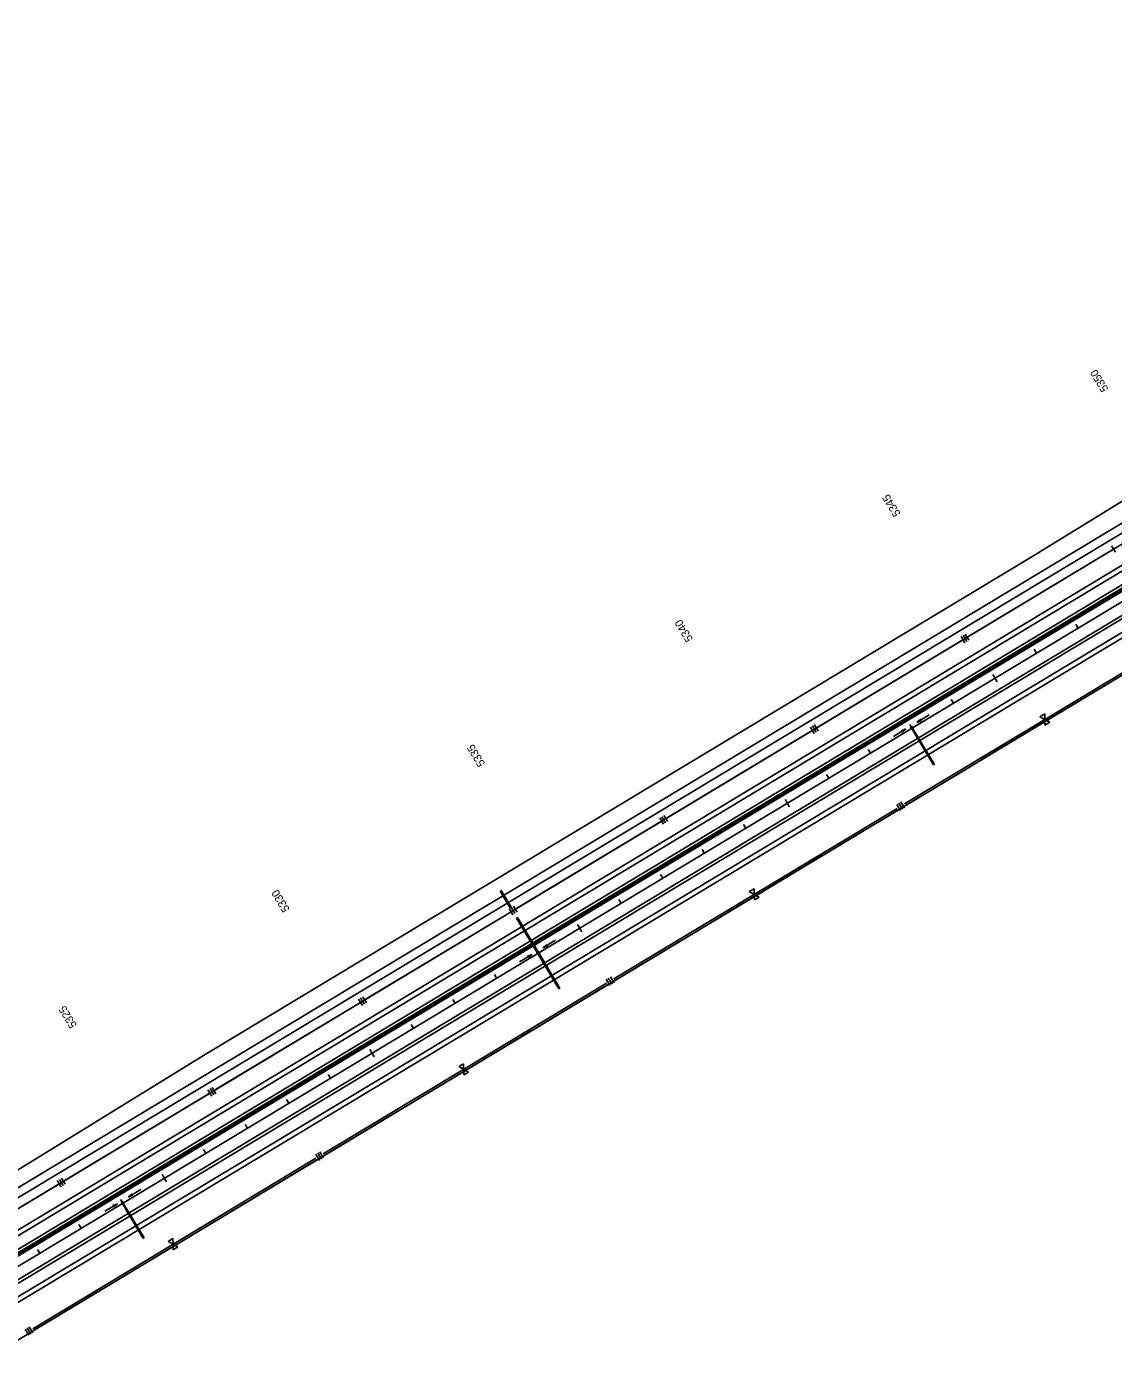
# Model space of a CAD drawing. Extents: x 192699 to 285914, y 194342 to 233219.
# Drawn here: x 275961 to 278202, y 228812 to 231567 of the extents above; entities that cross this region are included whole.
import ezdxf

# ---------------------------------------------------------------- set-up
doc = ezdxf.new("R2010")
doc.units = 0
for name, color, linetype in [('CENT LINE', 7, 'Continuous'), ('CONCRETE', 7, 'Continuous'), ('DRAINAGE', 7, 'Continuous'), ('DRAINAGE ARROWS', 7, 'Continuous'), ('R-W - CofA', 7, 'Continuous'), ('R_Water Annot', 7, 'Continuous'), ('ROAD', 7, 'Continuous'), ('SHOULDER', 7, 'Continuous'), ('STATIONING1', 7, 'Continuous'), ('WRSF', 7, 'Continuous')]:
    doc.layers.add(name, color=color, linetype=linetype)

msp = doc.modelspace()

# ---------------------------------------------------------------- linework, layer by layer
at = {"layer": 'CENT LINE'}
msp.add_line((271911, 226585.9), (279924.8, 231407.4), dxfattribs=at)
at = {"layer": 'CONCRETE'}
for p, q in [((271899.7, 226604.7), (279913.5, 231426.2)), ((271901.8, 226601.3), (279915.5, 231422.8))]:
    msp.add_line(p, q, dxfattribs=at)
at = {"layer": 'DRAINAGE'}
for p, q in [((277787.3, 230119), (277831.6, 230045.3)), ((277789, 230120), (277833.3, 230046.3)), ((277013.8, 229658.3), (276971, 229729.4)), ((277015.9, 229659.6), (276973.2, 229730.7)), ((277058.7, 229583.8), (277015.9, 229654.9)), ((277060.8, 229585), (277018, 229656.2)), ((276159.2, 229139.5), (276201.5, 229069.2)), ((276160.9, 229140.5), (276203.2, 229070.2))]:
    msp.add_line(p, q, dxfattribs=at)
for points in [[(277786.4, 230118.5), (277789.8, 230120.5), (277787.8, 230124), (277784.3, 230121.9)], [(277015.2, 229654.5), (277018.7, 229656.6), (277016.6, 229660), (277013.2, 229657.9)], [(276158.4, 229139), (276161.8, 229141), (276159.7, 229144.4), (276156.3, 229142.4)]]:
    msp.add_lwpolyline(points, close=True, dxfattribs=at)
for points in [[(277831.6, 230045.3), (277833.3, 230046.3)], [(276939.5, 229786.3), (276937.4, 229785.1)], [(276937.4, 229785.1), (276958, 229750.8)], [(276939.5, 229786.3), (276960.2, 229752.1)], [(276958, 229750.8), (276960.2, 229752.1)], [(276971, 229729.4), (276973.2, 229730.7)], [(277058.7, 229583.8), (277060.8, 229585)], [(276201.5, 229069.2), (276203.2, 229070.2)]]:
    msp.add_lwpolyline(points, dxfattribs=at)
at = {"layer": 'DRAINAGE ARROWS'}
for p, q in [((277805, 230139.5), (277797.3, 230133)), ((277806.6, 230136.9), (277805, 230139.5)), ((277765.4, 230115.5), (277774.7, 230119.4)), ((277767, 230112.9), (277765.4, 230115.5)), ((277765.5, 230115.3), (277773.3, 230118.5)), ((277765.7, 230115.1), (277771.8, 230117.6)), ((277765.8, 230114.9), (277770.4, 230116.8)), ((277765.9, 230114.6), (277769, 230115.9)), ((277766.1, 230114.4), (277767.5, 230115)), ((277766.3, 230114), (277767.5, 230115)), ((277766.4, 230113.8), (277769, 230115.9)), ((277766.6, 230113.6), (277770.4, 230116.8)), ((277766.7, 230113.4), (277771.8, 230117.6)), ((277766.8, 230113.2), (277773.3, 230118.5)), ((277767, 230112.9), (277774.7, 230119.4)), ((277806.6, 230136.9), (277797.3, 230133)), ((277805.2, 230139.3), (277798.7, 230133.9)), ((277806.5, 230137.2), (277798.7, 230133.9)), ((277805.3, 230139.1), (277800.2, 230134.8)), ((277806.3, 230137.4), (277800.2, 230134.8)), ((277805.4, 230138.9), (277801.6, 230135.7)), ((277806.2, 230137.6), (277801.6, 230135.7)), ((277805.5, 230138.6), (277803, 230136.5)), ((277806.1, 230137.8), (277803, 230136.5)), ((277805.7, 230138.4), (277804.5, 230137.4)), ((277805.9, 230138), (277804.5, 230137.4)), ((277033.7, 229674.7), (277025.9, 229668.2)), ((277035.2, 229672.1), (277025.9, 229668.2)), ((277033.8, 229674.5), (277027.3, 229669.1)), ((277035.1, 229672.3), (277027.3, 229669.1)), ((277033.9, 229674.2), (277028.8, 229670)), ((277035, 229672.5), (277028.8, 229670)), ((277034.1, 229674), (277030.2, 229670.8)), ((277034.8, 229672.8), (277030.2, 229670.8)), ((277034.2, 229673.8), (277031.7, 229671.7)), ((277034.7, 229673), (277031.7, 229671.7)), ((277034.3, 229673.6), (277033.1, 229672.6)), ((277034.6, 229673.2), (277033.1, 229672.6)), ((277035.2, 229672.1), (277033.7, 229674.7)), ((276994.1, 229650.7), (277003.4, 229654.6)), ((276995.6, 229648.1), (276994.1, 229650.7)), ((276994.2, 229650.5), (277002, 229653.7)), ((276994.3, 229650.2), (277000.5, 229652.8)), ((276994.4, 229650), (276999.1, 229651.9)), ((276994.6, 229649.8), (276997.6, 229651.1)), ((276994.7, 229649.6), (276996.2, 229650.2)), ((276995, 229649.2), (276996.2, 229650.2)), ((276995.1, 229649), (276997.6, 229651.1)), ((276995.2, 229648.8), (276999.1, 229651.9)), ((276995.3, 229648.5), (277000.5, 229652.8)), ((276995.5, 229648.3), (277002, 229653.7)), ((276995.6, 229648.1), (277003.4, 229654.6)), ((276178.3, 229160.7), (276170.5, 229154.2)), ((276179.8, 229158.1), (276170.5, 229154.2)), ((276178.4, 229160.5), (276171.9, 229155.1)), ((276179.7, 229158.4), (276171.9, 229155.1)), ((276178.5, 229160.3), (276173.4, 229156)), ((276179.6, 229158.6), (276173.4, 229156)), ((276178.7, 229160.1), (276174.8, 229156.8)), ((276179.4, 229158.8), (276174.8, 229156.8)), ((276178.8, 229159.8), (276176.3, 229157.7)), ((276179.3, 229159), (276176.3, 229157.7)), ((276178.9, 229159.6), (276177.7, 229158.6)), ((276179.2, 229159.2), (276177.7, 229158.6)), ((276179.8, 229158.1), (276178.3, 229160.7)), ((276138.7, 229136.7), (276148, 229140.6)), ((276140.2, 229134.1), (276138.7, 229136.7)), ((276138.8, 229136.5), (276146.6, 229139.7)), ((276138.9, 229136.3), (276145.1, 229138.8)), ((276139, 229136.1), (276143.7, 229138)), ((276139.2, 229135.8), (276142.2, 229137.1)), ((276139.3, 229135.6), (276140.8, 229136.2)), ((276139.5, 229135.2), (276140.8, 229136.2)), ((276139.7, 229135), (276142.2, 229137.1)), ((276139.8, 229134.8), (276143.7, 229138)), ((276139.9, 229134.6), (276145.1, 229138.8)), ((276140.1, 229134.4), (276146.6, 229139.7)), ((276140.2, 229134.1), (276148, 229140.6))]:
    msp.add_line(p, q, dxfattribs=at)
at = {"layer": 'R-W - CofA'}
for p, q in [((272764.3, 227218.3), (279147, 231058.4)), ((278199, 230496.8), (278206.7, 230483.9)), ((277888.3, 230309.9), (277896, 230297)), ((277892.6, 230312.5), (277900.3, 230299.6)), ((277896.9, 230315.1), (277904.6, 230302.2)), ((278051.1, 230144.7), (278061, 230150.6)), ((278061.2, 230139), (278051.1, 230144.7)), ((278061, 230150.6), (278061.2, 230139)), ((277577.6, 230123), (277585.3, 230110.1)), ((277581.9, 230125.6), (277589.6, 230112.7)), ((277586.2, 230128.2), (277593.9, 230115.3)), ((278061.4, 230127.4), (278061.2, 230139)), ((278061.2, 230139), (278071.4, 230133.4)), ((278071.4, 230133.4), (278061.4, 230127.4)), ((277756, 229964), (277763.6, 229951.3)), ((277760.2, 229966.5), (277767.8, 229953.9)), ((277764.4, 229969.1), (277772, 229956.4)), ((277266.9, 229936.1), (277274.6, 229923.2)), ((277271.2, 229938.6), (277278.9, 229925.7)), ((277275.5, 229941.2), (277283.2, 229928.3)), ((277451.6, 229784), (277461.6, 229790)), ((277461.8, 229778.4), (277451.6, 229784)), ((277461.6, 229790), (277461.8, 229778.4)), ((276964.8, 229754.3), (276972.5, 229741.4)), ((277462, 229766.8), (277461.8, 229778.4)), ((277461.8, 229778.4), (277471.9, 229772.8)), ((277471.9, 229772.8), (277462, 229766.8)), ((276956.2, 229749.1), (276963.9, 229736.2)), ((276960.5, 229751.7), (276968.2, 229738.8)), ((277156.5, 229603.3), (277164.1, 229590.7)), ((277160.7, 229605.9), (277168.4, 229593.2)), ((277165, 229608.4), (277172.6, 229595.8)), ((276645.5, 229562.2), (276653.3, 229549.3)), ((276649.8, 229564.8), (276657.6, 229551.9)), ((276654.1, 229567.4), (276661.9, 229554.5)), ((276852.2, 229423.3), (276862.1, 229429.3)), ((276862.3, 229417.7), (276852.2, 229423.3)), ((276862.1, 229429.3), (276862.3, 229417.7)), ((276862.6, 229406.1), (276862.3, 229417.7)), ((276862.3, 229417.7), (276872.5, 229412.1)), ((276872.5, 229412.1), (276862.6, 229406.1)), ((276334.8, 229375.3), (276342.6, 229362.4)), ((276339.1, 229377.9), (276346.9, 229365)), ((276343.4, 229380.4), (276351.2, 229367.5)), ((276557.1, 229242.7), (276564.7, 229230)), ((276561.3, 229245.2), (276568.9, 229232.6)), ((276565.5, 229247.8), (276573.1, 229235.1)), ((276024.1, 229188.3), (276031.9, 229175.4)), ((276028.4, 229190.9), (276036.2, 229178)), ((276032.7, 229193.5), (276040.5, 229180.6)), ((276252.8, 229062.7), (276262.7, 229068.7)), ((276262.7, 229068.7), (276262.9, 229057.1)), ((276262.9, 229057.1), (276252.8, 229062.7)), ((276263.1, 229045.5), (276262.9, 229057.1)), ((276262.9, 229057.1), (276273, 229051.4)), ((276273, 229051.4), (276263.1, 229045.5)), ((275957.6, 228882), (275965.3, 228869.4)), ((275961.9, 228884.6), (275969.5, 228871.9)), ((275966.1, 228887.1), (275973.7, 228874.4))]:
    msp.add_line(p, q, dxfattribs=at)
for points in [[(271987.3, 226783.5), (271997.7, 226911.1), (272381.7, 227079.1), (275038, 228677.3), (275469, 228930.8), (275900, 229184.3), (276325.9, 229446.3), (278039.6, 230477.4), (278465.5, 230739.4), (278707.1, 230919.8), (279091.3, 231151)], [(272284.5, 226658.8), (272466.2, 226744.8), (272638.9, 226848.7), (272798.6, 226968.2), (278625.3, 230473.8), (278892.7, 230611.3), (279276.9, 230842.5)], [(277904.2, 230310.7), (278199.4, 230488.3)], [(277904.2, 230310.7), (277904.2, 230310.7)], [(278066.2, 230142), (278355.9, 230316.3)], [(277593.5, 230123.8), (277888.7, 230301.4)], [(278068.2, 230138.7), (278201.5, 230218.8)], [(277771.6, 229964.8), (278066.2, 230142)], [(277282.8, 229936.9), (277578, 230114.5)], [(277593.5, 230123.8), (277593.5, 230123.8)], [(277930, 230055.5), (278068.2, 230138.7)], [(277773.6, 229961.4), (277906.9, 230041.6)], [(277911.2, 230044.2), (277916.3, 230047.2)], [(277920.6, 230049.8), (277925.7, 230052.9)], [(277466.8, 229781.4), (277756.4, 229955.6)], [(277625.2, 229872.1), (277758.4, 229952.3)], [(276972.1, 229749.9), (277267.3, 229927.5)], [(277282.8, 229936.8), (277282.8, 229936.9)], [(277606.3, 229860.8), (277611.5, 229863.8)], [(277615.8, 229866.4), (277620.9, 229869.5)], [(277468.8, 229778), (277602, 229858.2)], [(277172.1, 229604.1), (277466.8, 229781.4)], [(277330.6, 229694.8), (277468.8, 229778)], [(276661.4, 229563), (276956.6, 229740.6)], [(276972.1, 229749.9), (276972.1, 229749.9)], [(277174.2, 229600.7), (277307.4, 229680.9)], [(277311.7, 229683.5), (277316.9, 229686.6)], [(277321.1, 229689.2), (277326.3, 229692.3)], [(276867.3, 229420.7), (277157, 229595)], [(277025.7, 229511.4), (277159, 229591.6)], [(276661.4, 229563), (276661.4, 229563)], [(276350.7, 229376.1), (276645.9, 229553.7)], [(277016.3, 229505.8), (277021.5, 229508.9)], [(276869.3, 229417.3), (277002.6, 229497.5)], [(277006.9, 229500.1), (277012, 229503.2)], [(276572.7, 229243.5), (276867.3, 229420.7)], [(276731.1, 229334.2), (276869.3, 229417.3)], [(276350.7, 229376.1), (276350.7, 229376.1)], [(276040, 229189.1), (276335.2, 229366.7)], [(276574.7, 229240.1), (276708, 229320.3)], [(276712.3, 229322.8), (276717.4, 229325.9)], [(276721.7, 229328.5), (276726.8, 229331.6)], [(276267.9, 229060.1), (276557.5, 229234.3)], [(276426.3, 229150.8), (276559.5, 229230.9)], [(275729.3, 229002.2), (276024.5, 229179.8)], [(276040, 229189.1), (276040, 229189.1)], [(276416.9, 229145.1), (276422, 229148.2)], [(276269.9, 229056.7), (276403.2, 229136.9)], [(276407.4, 229139.4), (276412.6, 229142.5)], [(275973.3, 228882.8), (276267.9, 229060.1)], [(276131.7, 228973.5), (276269.9, 229056.7)], [(275975.3, 228879.4), (276108.5, 228959.6)], [(276112.8, 228962.2), (276118, 228965.3)], [(276122.2, 228967.8), (276127.4, 228970.9)]]:
    msp.add_lwpolyline(points, dxfattribs=at)
at = {"layer": 'R_Water Annot'}
for p, q in [((277822.9, 230148.6), (277797.3, 230133)), ((277805, 230139.5), (277797.3, 230133)), ((277806.6, 230136.9), (277805, 230139.5)), ((277749.1, 230103.9), (277774.7, 230119.4)), ((277765.4, 230115.5), (277774.7, 230119.4)), ((277767, 230112.9), (277765.4, 230115.5)), ((277765.5, 230115.3), (277773.3, 230118.5)), ((277765.7, 230115.1), (277771.8, 230117.6)), ((277765.8, 230114.9), (277770.4, 230116.8)), ((277765.9, 230114.6), (277769, 230115.9)), ((277766.1, 230114.4), (277767.5, 230115)), ((277766.3, 230114), (277767.5, 230115)), ((277766.4, 230113.8), (277769, 230115.9)), ((277766.6, 230113.6), (277770.4, 230116.8)), ((277766.7, 230113.4), (277771.8, 230117.6)), ((277766.8, 230113.2), (277773.3, 230118.5)), ((277767, 230112.9), (277774.7, 230119.4)), ((277806.6, 230136.9), (277797.3, 230133)), ((277805.2, 230139.3), (277798.7, 230133.9)), ((277806.5, 230137.2), (277798.7, 230133.9)), ((277805.3, 230139.1), (277800.2, 230134.8)), ((277806.3, 230137.4), (277800.2, 230134.8)), ((277805.4, 230138.9), (277801.6, 230135.7)), ((277806.2, 230137.6), (277801.6, 230135.7)), ((277805.5, 230138.6), (277803, 230136.5)), ((277806.1, 230137.8), (277803, 230136.5)), ((277805.7, 230138.4), (277804.5, 230137.4)), ((277805.9, 230138), (277804.5, 230137.4)), ((277051.5, 229683.8), (277025.9, 229668.2)), ((277033.7, 229674.7), (277025.9, 229668.2)), ((277035.2, 229672.1), (277025.9, 229668.2)), ((277033.8, 229674.5), (277027.3, 229669.1)), ((277035.1, 229672.3), (277027.3, 229669.1)), ((277033.9, 229674.2), (277028.8, 229670)), ((277035, 229672.5), (277028.8, 229670)), ((277034.1, 229674), (277030.2, 229670.8)), ((277034.8, 229672.8), (277030.2, 229670.8)), ((277034.2, 229673.8), (277031.7, 229671.7)), ((277034.7, 229673), (277031.7, 229671.7)), ((277034.3, 229673.6), (277033.1, 229672.6)), ((277034.6, 229673.2), (277033.1, 229672.6)), ((277035.2, 229672.1), (277033.7, 229674.7)), ((276977.7, 229639.1), (277003.4, 229654.6)), ((276994.1, 229650.7), (277003.4, 229654.6)), ((276995.6, 229648.1), (276994.1, 229650.7)), ((276994.2, 229650.5), (277002, 229653.7)), ((276994.3, 229650.2), (277000.5, 229652.8)), ((276994.4, 229650), (276999.1, 229651.9)), ((276994.6, 229649.8), (276997.6, 229651.1)), ((276994.7, 229649.6), (276996.2, 229650.2)), ((276995, 229649.2), (276996.2, 229650.2)), ((276995.1, 229649), (276997.6, 229651.1)), ((276995.2, 229648.8), (276999.1, 229651.9)), ((276995.3, 229648.5), (277000.5, 229652.8)), ((276995.5, 229648.3), (277002, 229653.7)), ((276995.6, 229648.1), (277003.4, 229654.6)), ((276196.1, 229169.8), (276170.5, 229154.2)), ((276178.3, 229160.7), (276170.5, 229154.2)), ((276179.8, 229158.1), (276170.5, 229154.2)), ((276178.4, 229160.5), (276171.9, 229155.1)), ((276179.7, 229158.4), (276171.9, 229155.1)), ((276178.5, 229160.3), (276173.4, 229156)), ((276179.6, 229158.6), (276173.4, 229156)), ((276178.7, 229160.1), (276174.8, 229156.8)), ((276179.4, 229158.8), (276174.8, 229156.8)), ((276178.8, 229159.8), (276176.3, 229157.7)), ((276179.3, 229159), (276176.3, 229157.7)), ((276178.9, 229159.6), (276177.7, 229158.6)), ((276179.2, 229159.2), (276177.7, 229158.6)), ((276179.8, 229158.1), (276178.3, 229160.7)), ((276122.3, 229125.1), (276148, 229140.6)), ((276138.7, 229136.7), (276148, 229140.6)), ((276140.2, 229134.1), (276138.7, 229136.7)), ((276138.8, 229136.5), (276146.6, 229139.7)), ((276138.9, 229136.3), (276145.1, 229138.8)), ((276139, 229136.1), (276143.7, 229138)), ((276139.2, 229135.8), (276142.2, 229137.1)), ((276139.3, 229135.6), (276140.8, 229136.2)), ((276139.5, 229135.2), (276140.8, 229136.2)), ((276139.7, 229135), (276142.2, 229137.1)), ((276139.8, 229134.8), (276143.7, 229138)), ((276139.9, 229134.6), (276145.1, 229138.8)), ((276140.1, 229134.4), (276146.6, 229139.7)), ((276140.2, 229134.1), (276148, 229140.6))]:
    msp.add_line(p, q, dxfattribs=at)
at = {"layer": 'ROAD'}
for p, q in [((271883.2, 226632.1), (280071.4, 231558.6)), ((272745.6, 227250.2), (279885, 231545.6)), ((272754.9, 227234.8), (279894.2, 231530.2)), ((271895.6, 226611.6), (279909.3, 231433.1)), ((271926.5, 226560.2), (279942, 231382.7)), ((271938.9, 226539.6), (279952.6, 231361.1))]:
    msp.add_line(p, q, dxfattribs=at)
at = {"layer": 'SHOULDER'}
for p, q in [((271878, 226640.7), (280066.3, 231567.2)), ((271898.7, 226606.4), (279912.4, 231427.9)), ((271923.4, 226565.3), (279938.9, 231387.9)), ((271944, 226531), (279957.8, 231352.5))]:
    msp.add_line(p, q, dxfattribs=at)
at = {"layer": 'STATIONING1'}
for points in [[(278125.2, 230335.1), (278129.8, 230327.4)], [(278039.5, 230283.6), (278044.1, 230275.9)], [(277953.8, 230232), (277963.1, 230216.6)], [(277868.1, 230180.5), (277872.8, 230172.8)], [(277782.4, 230128.9), (277787.1, 230121.2)], [(277696.8, 230077.4), (277701.4, 230069.7)], [(277611.1, 230025.8), (277615.7, 230018.1)], [(277525.4, 229974.3), (277534.7, 229958.8)], [(277439.7, 229922.7), (277444.3, 229915)], [(277354, 229871.2), (277358.7, 229863.4)], [(277268.3, 229819.6), (277273, 229811.9)], [(277182.6, 229768.1), (277187.3, 229760.3)], [(277097, 229716.5), (277106.2, 229701.1)], [(277011.3, 229664.9), (277015.9, 229657.2)], [(276925.6, 229613.4), (276930.2, 229605.7)], [(276839.9, 229561.8), (276844.5, 229554.1)], [(276754.2, 229510.3), (276758.8, 229502.6)], [(276668.5, 229458.7), (276677.8, 229443.3)], [(276582.8, 229407.2), (276587.5, 229399.5)], [(276497.1, 229355.6), (276501.8, 229347.9)], [(276411.5, 229304.1), (276416.1, 229296.4)], [(276325.8, 229252.5), (276330.4, 229244.8)], [(276240.1, 229201), (276249.4, 229185.5)], [(276154.4, 229149.4), (276159, 229141.7)], [(276068.7, 229097.9), (276073.4, 229090.1)], [(275983, 229046.3), (275987.7, 229038.6)]]:
    msp.add_lwpolyline(points, dxfattribs=at)
at = {"layer": 'WRSF'}
msp.add_line((271900.7, 226603), (279914.5, 231424.5), dxfattribs=at)

# ---------------------------------------------------------------- texts
at = {"layer": 'STATIONING1'}
for s, p in [('5350', (278193, 230820.3)), ('5345', (277764.3, 230563.1)), ('5340', (277336.2, 230304.8)), ('5335', (276907.4, 230047.6)), ('5330', (276504.2, 229747.8)), ('5325', (276065.2, 229508.5))]:
    msp.add_text(s, height=16.5, rotation=121.0333, dxfattribs=at).set_placement(p)

doc.saveas('drawing.dxf')
